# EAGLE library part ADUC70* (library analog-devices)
Precision Analog Microcontroller 12-bit Analog I/O, ARM7TDMI® MCU ADuC7019/ADuC7020 Source: http://www.analog.com/UploadedFiles/Data_Sheets/288945048AD7C7019_20_1_2_4_5_6_7_0.pdf
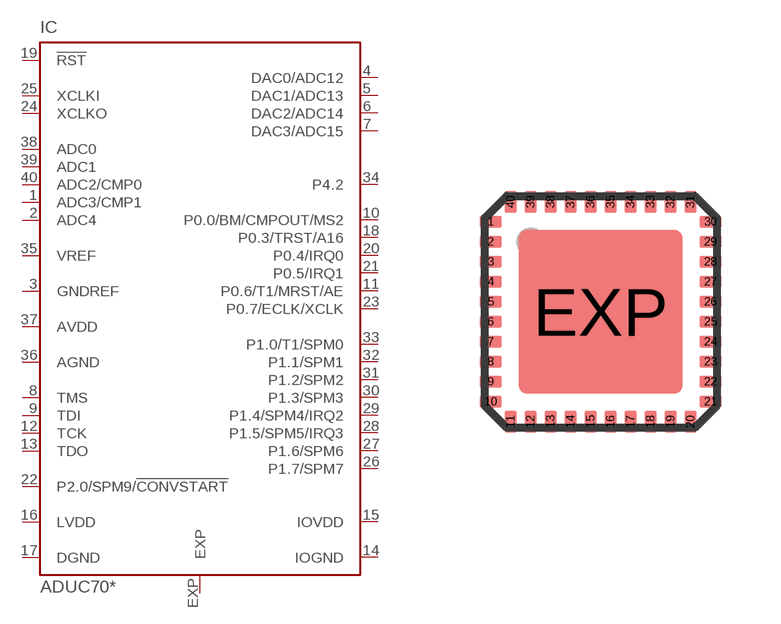
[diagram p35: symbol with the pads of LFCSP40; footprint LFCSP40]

Designator prefix IC

## ADUC7019BCPZ62I (MPN: ADUC7019BCPZ62I; OC_FARNELL: unknown; OC_NEWARK: 19M0734), ADUC7019BCPZ62I-RL (MPN: ADUC7019BCPZ62IRL7; OC_FARNELL: unknown; OC_NEWARK: 12M8312), ADUC7019BCPZ62IRL7 (MPN: ADUC7019BCPZ62IRL7; OC_FARNELL: unknown; OC_NEWARK: 12M8312), ADUC7020BCPZ62 (MPN: ADUC7020BCPZ62; OC_FARNELL: 1162634; OC_NEWARK: 19M0735), ADUC7020BCPZ62-RL (MPN: ADUC7020BCPZ62-RL7; OC_FARNELL: unknown; OC_NEWARK: 12M8315), ADUC7020BCPZ62-RL7 (OC_FARNELL: unknown; OC_NEWARK: unknown), ADUC7020BCPZ62I (MPN: ADUC7020BCPZ62I; OC_FARNELL: unknown; OC_NEWARK: 61M4009), ADUC7020BCPZ62I-RL (MPN: ADUC7020BCPZ62I-RL; OC_FARNELL: unknown; OC_NEWARK: 12M8316), ADUC7020BCPZ62IRL7 (MPN: ADUC7020BCPZ62IRL7; OC_FARNELL: unknown; OC_NEWARK: 12M8317)  [LFCSP40]
1  ADC3/CMP1  in
2  ADC4  in
3  GNDREF  in
4  DAC0/ADC12  in
5  DAC1/ADC13  in
6  DAC2/ADC14  in
7  DAC3/ADC15  in
8  TMS  in
9  TDI  in
10  P0.0/BM/CMPOUT/MS2
11  P0.6/T1/MRST/AE
12  TCK  in
13  TDO  out
14  IOGND  pwr
15  IOVDD  pwr
16  LVDD  out
17  DGND  pwr
18  P0.3/TRST/A16
19  !RST  in
20  P0.4/IRQ0
21  P0.5/IRQ1
22  P2.0/SPM9/!CONVSTART
23  P0.7/ECLK/XCLK
24  XCLKO  out
25  XCLKI  in
26  P1.7/SPM7
27  P1.6/SPM6
28  P1.5/SPM5/IRQ3
29  P1.4/SPM4/IRQ2
30  P1.3/SPM3
31  P1.2/SPM2
32  P1.1/SPM1
33  P1.0/T1/SPM0
34  P4.2
35  VREF  pas
36  AGND  pwr
37  AVDD  pwr
38  ADC0  in
39  ADC1  in
40  ADC2/CMP0  in
EXP  EXP  pas

## Footprint LFCSP40 (pad centres in mm)
40-Lead Frame Chip Scale Package [LFCSP_VQ] 6 mm x 6 mm Body, Very Thin Quad (CP-40) COMPLIANT TO JEDEC STANDARDS MO-220-VJJD-2 Source: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
smd 0.55 x 0.3: 1 -2.75,2.25; 2 -2.75,1.75; 3 -2.75,1.25; 4 -2.75,0.75; 5 -2.75,0.25; 6 -2.75,-0.25; 7 -2.75,-0.75; 8 -2.75,-1.25; 9 -2.75,-1.75; 10 -2.75,-2.25; 21 2.75,-2.25; 22 2.75,-1.75; 23 2.75,-1.25; 24 2.75,-0.75; 25 2.75,-0.25; 26 2.75,0.25; 27 2.75,0.75; 28 2.75,1.25; 29 2.75,1.75; 30 2.75,2.25
smd 0.3 x 0.55: 11 -2.25,-2.75; 12 -1.75,-2.75; 13 -1.25,-2.75; 14 -0.75,-2.75; 15 -0.25,-2.75; 16 0.25,-2.75; 17 0.75,-2.75; 18 1.25,-2.75; 19 1.75,-2.75; 20 2.25,-2.75; 31 2.25,2.75; 32 1.75,2.75; 33 1.25,2.75; 34 0.75,2.75; 35 0.25,2.75; 36 -0.25,2.75; 37 -0.75,2.75; 38 -1.25,2.75; 39 -1.75,2.75; 40 -2.25,2.75
smd 4.1 x 4.1: EXP 0,0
